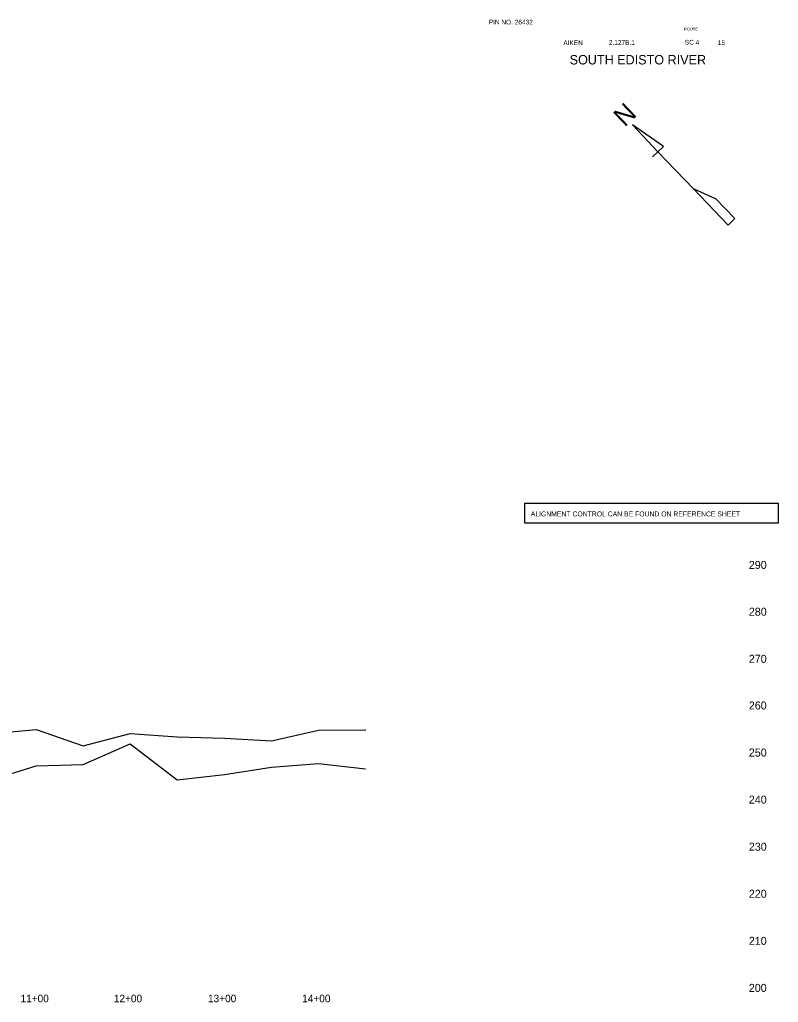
# Model space of a CAD drawing. Extents: x 52056 to 55012, y 51514 to 52558.
# Drawn here: x 54206 to 55012, y 51514 to 52558 of the extents above; entities that cross this region are included whole.
import ezdxf

# ---------------------------------------------------------------- set-up
doc = ezdxf.new("R2010")
doc.units = 0
for name, color, linetype in [('Level 1', 7, 'Continuous'), ('Level 2', 7, 'Continuous'), ('Level 24', 7, 'Continuous'), ('Level 25', 7, 'Continuous'), ('Level 40', 7, 'Continuous'), ('Level 42', 7, 'Continuous')]:
    doc.layers.add(name, color=color, linetype=linetype)

msp = doc.modelspace()

# ---------------------------------------------------------------- linework, layer by layer
at = {"layer": 'Level 2'}
for p, q in [((54889.5, 52423), (54856.7, 52446)), ((54856.7, 52446), (54856.7, 52446)), ((54856.7, 52446), (54883.8, 52417.6)), ((54878.1, 52412.2), (54883.8, 52417.6)), ((54883.8, 52417.6), (54889.5, 52423)), ((54921.4, 52378.3), (54883.8, 52417.6)), ((54889.5, 52423), (54889.1, 52423.4)), ((54945, 52367.7), (54921.4, 52378.3)), ((54921.4, 52378.3), (54958.3, 52339.7)), ((54965.4, 52346.5), (54944.9, 52367.9)), ((54944.9, 52367.9), (54945, 52367.7)), ((54958.3, 52339.7), (54965.4, 52346.5))]:
    msp.add_line(p, q, dxfattribs=at)
at = {"layer": 'Level 25'}
msp.add_lwpolyline([(54742.3, 52044.4), (55011.6, 52044.4), (55011.6, 52023.1), (54742.3, 52023.1)], close=True, dxfattribs=at)
at = {"layer": 'Level 40'}
for points in [[(54173.3, 51799.4), (54223.3, 51803.9), (54273.3, 51786.5), (54323.3, 51799.5), (54373.3, 51796.1), (54423.3, 51794.7), (54473.3, 51791.9), (54523.3, 51803), (54573.3, 51803.4), (54573.4, 51803.4)], [(53423.3, 51762.2), (53473.3, 51763.9), (53523.3, 51761.1), (53573.3, 51764.8), (53623.3, 51770.4), (53673.3, 51759.3), (53723.3, 51762.5), (53773.3, 51772.4), (53823.3, 51759.9), (53873.3, 51760.2), (53923.3, 51754.6), (53973.3, 51750.5), (54023.3, 51753.5), (54073.3, 51754.6), (54123.3, 51763.5), (54173.3, 51749.6), (54223.3, 51765.1), (54273.3, 51766.7), (54323.3, 51788.6), (54373.3, 51750.4), (54423.3, 51756.1), (54473.3, 51764), (54523.3, 51767.8), (54573.3, 51762.2)]]:
    msp.add_lwpolyline(points, dxfattribs=at)

# ---------------------------------------------------------------- texts
at = {"layer": 'Level 1'}
msp.add_text('ROUTE', height=3, dxfattribs=at).set_placement((54911.6, 52546.5))
at = {"layer": 'Level 2'}
msp.add_text('N', height=20, rotation=43.6976, dxfattribs=at).set_placement((54848.4, 52443.2))
at = {"layer": 'Level 24'}
for s, height, p in [('PIN NO. 26432', 5, (54704.1, 52552.8)), ('AIKEN', 5, (54783.3, 52530.8)), (' 2.127B.1', 5, (54829.7, 52531.1)), ('SC 4', 5, (54912.3, 52531.4)), ('15', 5, (54947.4, 52531)), ('SOUTH EDISTO RIVER', 10, (54790, 52510.3))]:
    msp.add_text(s, height=height, dxfattribs=at).set_placement(p)
at = {"layer": 'Level 25'}
msp.add_text('ALIGNMENT CONTROL CAN BE FOUND ON REFERENCE SHEET', height=5.25, dxfattribs=at).set_placement((54748.7, 52030.2))
at = {"layer": 'Level 42'}
for s, height, p in [('290', 8.5, (54980.3, 51974.4)), ('280', 8.5, (54980.3, 51924.7)), ('270', 8.5, (54980.3, 51874.7)), ('260', 8.5, (54980.3, 51825.1)), ('250', 8.5, (54980.3, 51775.1)), ('240', 8.5, (54980.3, 51725.1)), ('230', 8.5, (54980.3, 51675.1)), ('220', 8.5, (54980.3, 51625.1)), ('210', 8.5, (54980.3, 51575.1)), ('200', 8.5, (54980.3, 51525.1)), ('11+00', 8, (54206.8, 51514.1)), ('12+00', 8, (54305.9, 51514.1)), ('13+00', 8, (54405.9, 51514.1)), ('14+00', 8, (54505.9, 51514.1))]:
    msp.add_text(s, height=height, dxfattribs=at).set_placement(p)

doc.saveas('drawing.dxf')
